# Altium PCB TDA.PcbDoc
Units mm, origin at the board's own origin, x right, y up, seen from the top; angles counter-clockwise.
Board outline 70 x 30 mm, 2 copper layers (Top Layer, Bottom Layer); 24 components, 16 nets, 55 pads, 0 vias.
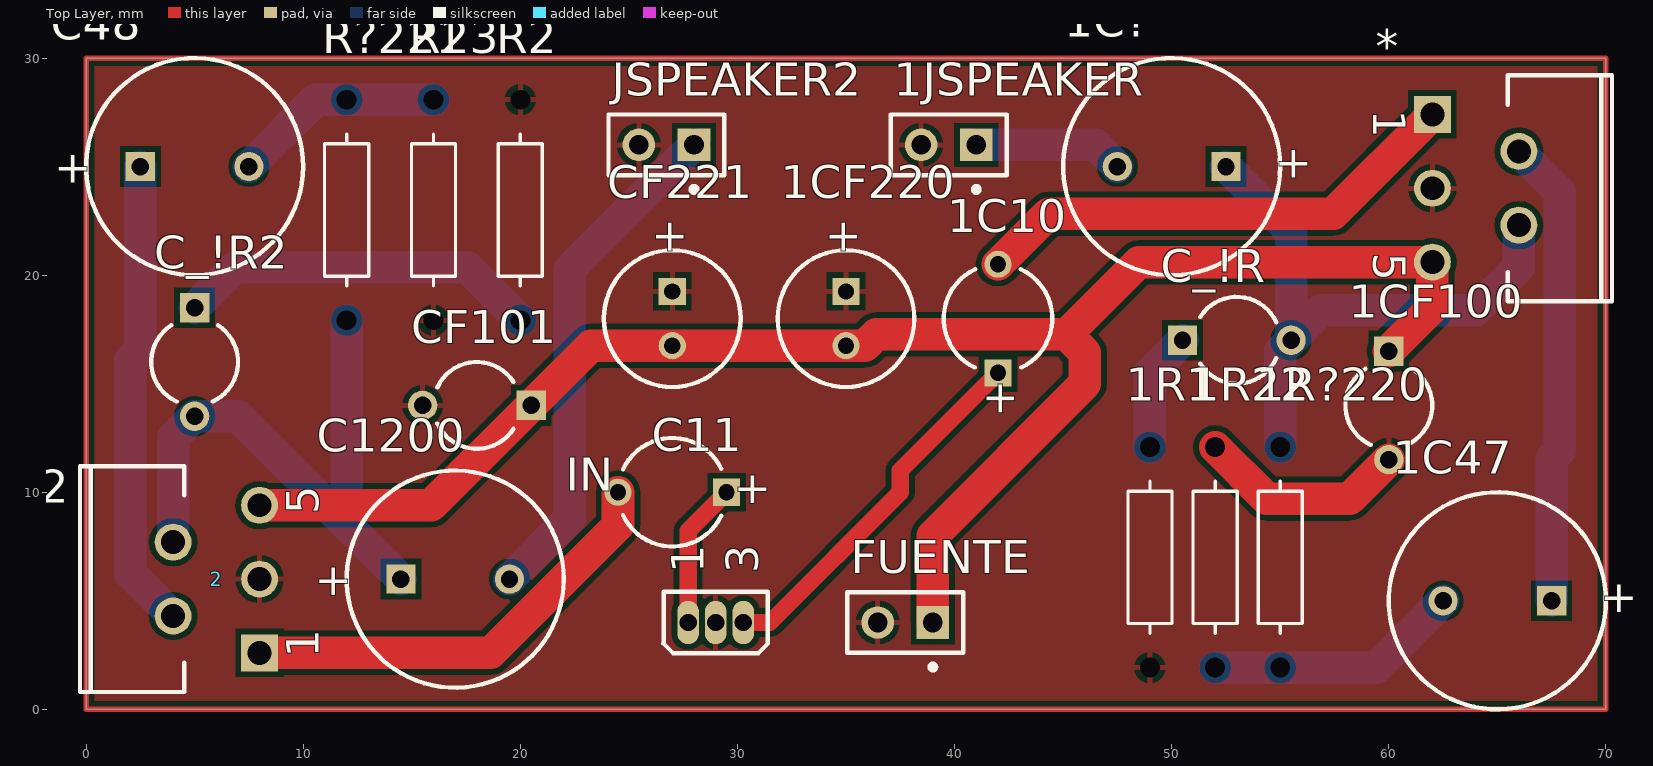
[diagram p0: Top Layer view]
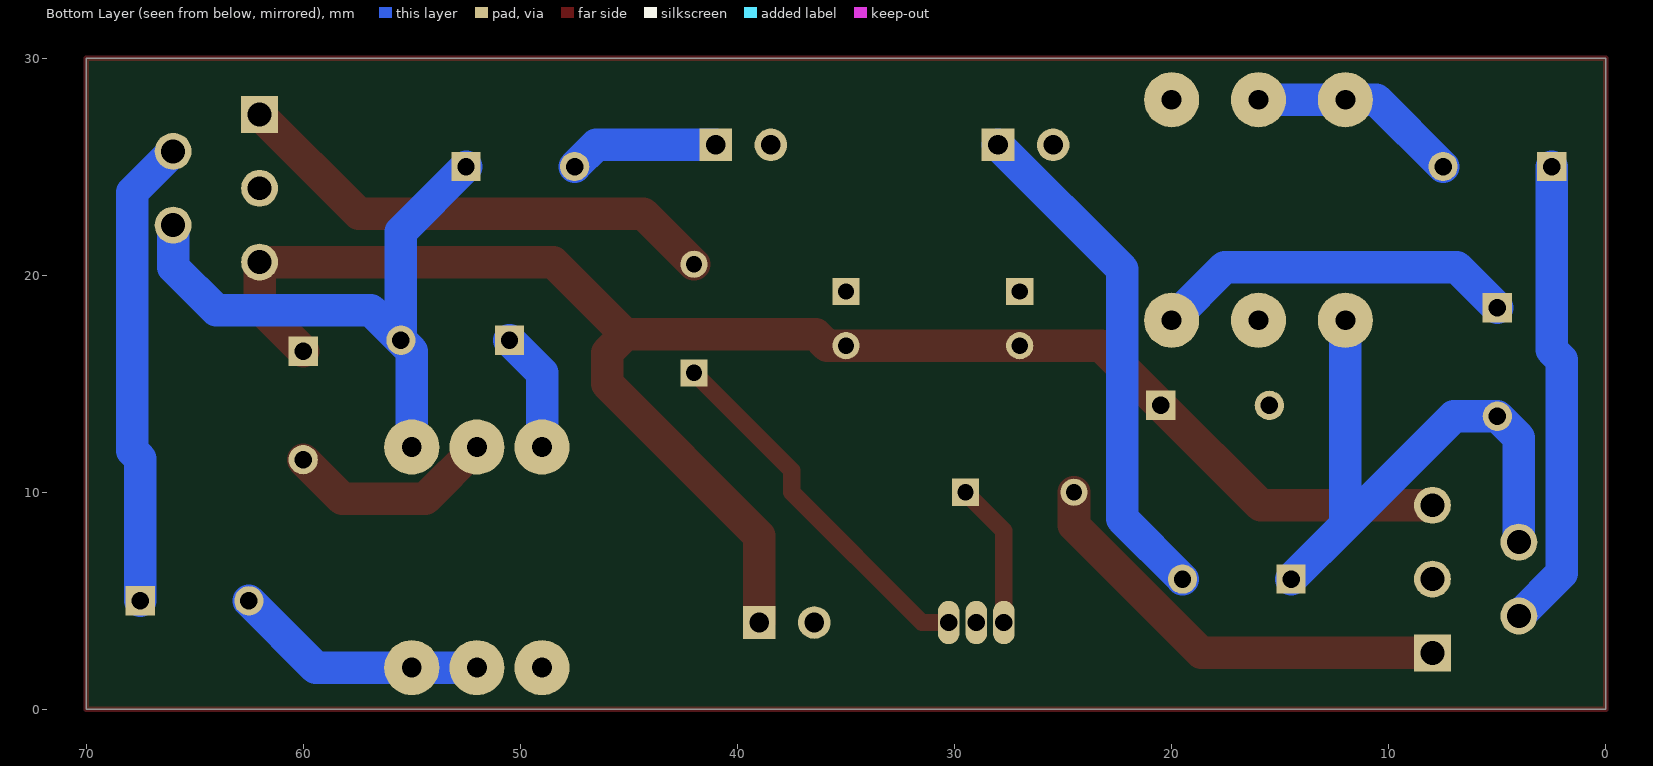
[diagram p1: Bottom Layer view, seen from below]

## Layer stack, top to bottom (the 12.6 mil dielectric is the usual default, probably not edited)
Top Solder: solder mask 0.0102, Solder Resist, Dk 3.5
Top Layer: signal copper 0.0356
Dielectric 1: dielectric 0.32, FR-4, Dk 4.8
Bottom Layer: signal copper 0.0356
Bottom Solder: solder mask 0.0102, Solder Resist, Dk 3.5

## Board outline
0,0 70,0 70,30 0,30

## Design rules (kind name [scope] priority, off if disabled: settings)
Clearance [All] p1: gap=0.254
PolygonConnect [All] p1: connectstyle=Relief reliefconductorwidth=0.254 reliefentries=4 polygonreliefangle="90 Angle" airgapwidth=0.254
RoomDefinition Tda2002 [InComponentClass('Tda2002')] p1: confinementstyle=ConfineIn formatcopy=TRUE lockcomponents=FALSE outline -25.4,-25.4 25.4,-25.4 25.4,0 -25.4,0
RoutingLayers RoutingLayers_arriba [InNetClass('arriba')] p1: top layer_v5=TRUE bottom layer_v5=FALSE
RoutingLayers [All] p2: top layer_v5=FALSE bottom layer_v5=TRUE
RoutingVias [All] p1: holewidth=0.711 width=1.27 viastyle="Through Hole" minholewidth=0.711 minwidth=1.27 maxholewidth=0.711 maxwidth=1.27
SolderMaskExpansion [All] p1: expansion=0.102
Width [All] p1: maxlimit=1.825 minlimit=0.254 preferedwidth=1.5
29 further rules are at their usual default settings.

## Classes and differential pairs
net class arriba: GND IN1 IN1FIL IN2 IN2FIL VCC

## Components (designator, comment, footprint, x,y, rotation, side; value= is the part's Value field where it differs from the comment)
1C10 "Cap 10" CAPPR5-5X7 42,18 r90 top
1C47 "Cap P470" cappr5-10x5 65,5 r180 top
1C? "Cap 1000" cappr5-10x5 50,25 r180 top
1CF100 "Cap Pol1" CAPR5-4X5 60,14 r270 top
1CF220 "Cap" cappr2.5-6.3x7 35,18 r270 top
1JSPEAKER "2P_TERM_BLOCK_HEADER" PIN2 41,26 r180 top
1R1 "Res2" RESTH_AXIAL-0.4 49,7 r270 top
1R22 "Res2" RESTH_AXIAL-0.4 52,7 r270 top
1R?220 "Res2" RESTH_AXIAL-0.4 55,7 r90 top
2 "TDA2002" PentawattV 6,6 r90 top
* "TDA2002" PentawattV 64,24 r270 top
C11 "Cap 10" CAPPR5-5X7 27,10 r180 top
C48 "Cap P470" cappr5-10x5 5,25 r0 top
C1200 "Cap 1000" cappr5-10x5 17,6 r0 top
C_!R "Cap" CAPR5-4X5 53,17 r0 top
C_!R2 "Cap" CAPR5-4X5 5,16 r270 top
CF101 "Cap Pol1" CAPR5-4X5 18,14 r180 top
CF221 "Cap" cappr2.5-6.3x7 27,18 r270 top
FUENTE "2P_TERM_BLOCK_HEADER" pin2 39,4 r180 top
IN "3P_TERM BLOCK HEADER" E3 29,4 r90 top
JSPEAKER2 "2P_TERM_BLOCK_HEADER" pin2 28,26 r180 top
R2 "Res2" RESTH_AXIAL-0.4 20,23 r90 top
R23 "Res2" RESTH_AXIAL-0.4 16,23 r90 top
R?221 "Res2w" RESTH_AXIAL-0.4 12,23 r270 top

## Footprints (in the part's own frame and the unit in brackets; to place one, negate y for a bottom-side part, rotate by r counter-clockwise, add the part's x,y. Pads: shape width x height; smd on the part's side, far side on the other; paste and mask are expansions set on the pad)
cappr2.5-6.3x7 [mm] "Capacitor, Electrolytic, Radial; Body 6.3 x 7 mm (Dia.xH typ); Pin Spacing 2.5 mm (typ)"
  rect 1.25x1.25 hole 0.75: 1(-1.25,0)
  round 1.25 hole 0.75: 2(1.25,0)
  silkscreen extent -3.15,-3.15 3.15,3.15
CAPPR5-5X7 [mm] "Capacitor, Electrolytic, Radial; Body 5 x 7 mm (Dia.xH typ); Pin Spacing 5 mm (typ)"
  rect 1.25x1.25 hole 0.75: 1(-2.5,0)
  round 1.25 hole 0.75: 2(2.5,0)
  silkscreen extent -2.26,-2.5 2.27,2.5
cappr5-10x5 [mm] "Capacitor, Electrolytic, Radial; Body 10 x 5 mm (Dia.xH typ); Pin Spacing 5 mm (typ)"
  rect 1.35x1.35 hole 0.8: 1(-2.5,0)
  round 1.35 hole 0.8: 2(2.5,0)
  silkscreen extent -5,-5 5,5
CAPR5-4X5 [mm] "Capacitor; 2 Leads"
  rect 1.35x1.35 hole 0.8: 1(-2.5,0)
  round 1.35 hole 0.8: 2(2.5,0)
  silkscreen extent -1.69,-2 1.82,2
E3 [mm] "TO, Flat Index; 3 In-Line, Axial Leads; Body Dia. 4.6mm; Lead Dia. 0.5 mm (max)"
  oval 2x1 hole 0.8: 1(0,1.27) 2(0,0) 3(0,-1.27)
  silkscreen extent -1.41,-2.41 1.41,2.41
PentawattV [mm] "TO, Thru-Hole, Vertical, Heatsink Mounted; 5 Bent Staggered Leads; Pitch 1.7 mm"
  rect 1.7x1.7 hole 1.1: 1(-3.4,-1.99)
  round 1.7 hole 1.1: 2(-1.7,1.99) 3(0,-1.99) 4(1.7,1.99) 5(3.4,-1.99)
  silkscreen extent -5.2,1.48 5.2,6.28
PIN2 [mm] "Photosensitive Diode; 2 Leads"
  rect 1.5x1.5 hole 0.9: 1(0,0)
  round 1.5 hole 0.9: 2(2.54,0)
  silkscreen extent -1.4,-1.4 3.94,2.17
pin2 [mm] "Photosensitive Diode; 2 Leads"
  rect 1.5x1.5 hole 0.9: 1(0,0)
  round 1.5 hole 0.9: 2(2.54,0)
  silkscreen extent -1.4,-1.4 3.94,2.17
RESTH_AXIAL-0.4 [mil]
  round 0 / inner round 0 / far side round 100 hole 36 unplated: 1(-200,0) 2(200,0)
  silkscreen extent -138,-40 138,40, body extent -212,-50 212,50, height 102

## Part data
1C10 1C47 1C? C11 C48 C1200: library part "Cap Pol1", "Polarized Capacitor (Radial)"
1CF100 CF101: "Polarized Capacitor (Radial)"
1CF220 C_!R C_!R2 CF221: "Capacitor"
1JSPEAKER FUENTE JSPEAKER2: "Terminal Block THT 2-position header 3.81mm pitch"
1R1 1R22 1R?220 R2 R23: "Resistor"
IN: "Terminal Block THT 3-Position header 3.81mm pitch"
R?221: library part Res2, "Resistor"

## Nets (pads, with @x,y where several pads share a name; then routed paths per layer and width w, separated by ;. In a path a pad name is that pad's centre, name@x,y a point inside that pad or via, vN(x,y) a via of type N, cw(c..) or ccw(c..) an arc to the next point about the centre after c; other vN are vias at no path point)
GND: 1CF100.2 1CF220.1 1JSPEAKER.2 1R1.2 1R22.1 2.3 *.3 CF101.2 CF221.1 FUENTE.2 IN.2 JSPEAKER2.2 R2.2 R23.1 | length 9.7
  Top Layer w1.5: 1R22.1 54.377,9.703 58.203,9.703 1CF100.2
IN1: 1C10.1 IN.3 | length 17.1
  Top Layer w0.8: IN.3 31.5,4 37.5,10 37.5,11 1C10.1
IN1FIL: 1C10.2 *.1 | length 22.9
  Top Layer w1.5: 1C10.2 44.335,22.835 57.445,22.835 *.1
IN2: C11.1 IN.1 | length 6.7
  Top Layer w0.8: IN.1 27.73,8.23 C11.1
IN2FIL: 2.1 C11.2 | length 20.5
  Top Layer w1.5: 2.1 18.627,2.6 24.5,8.473 C11.2
Net1C47_2: 1C47.2 1R22.2 1R?220.1 | length 11.8
  Bottom Layer w1.5: 1R22.2 1R?220.1 59.42,1.92 1C47.2
Net1C?_2: 1C?.2 1JSPEAKER.1 | length 6.9
  Bottom Layer w1.5: 1JSPEAKER.1 46.5,26 1C?.2
Net1R1_1: 1R1.1 C_!R.1 | length 5.5
  Bottom Layer w1.5: 1R1.1 49,15.5 C_!R.1
Net2_2: 2.2 C48.1 | length 21.7
  Bottom Layer w1.5: C48.1 2.5,16.561 2.032,16.093 2.032,6.278 2.2
Net2_4: 2.4 C1200.1 C_!R2.2 R?221.2 | length 28.2
  Bottom Layer w1.5: 2.4 4.01,12.51 C_!R2.2 7,13.5 12,8.5 ; R?221.2 12,8.5 ; C1200.1 12,8.5
Net*_2: 1C47.1 *.2 | length 21.6
  Bottom Layer w1.5: *.2 67.869,23.821 67.869,11.913 67.5,11.544 1C47.1
Net*_4: 1C?.1 1R?220.2 *.4 C_!R.2 | length 28.2
  Bottom Layer w1.5: 1C?.1 55.5,22 C_!R.2 ; 1R?220.2 55,16.5 C_!R.2 ; *.4 65.99,20.372 64.008,18.39 56.89,18.39 C_!R.2
NetC48_2: C48.2 R23.2 R?221.1 | length 9.8
  Bottom Layer w1.5: C48.2 10.58,28.08 R?221.1 R23.2
NetC1200_2: C1200.2 JSPEAKER2.1 | length 23.5
  Bottom Layer w1.5: C1200.2 22.276,8.776 22.276,20.276 JSPEAKER2.1
NetC_!R2_1: C_!R2.1 R2.1 | length 16.8
  Bottom Layer w1.5: C_!R2.1 6.867,20.367 17.553,20.367 R2.1
VCC: 1CF100.1 1CF220.2 2.5 *.5 CF101.1 CF221.2 FUENTE.1 | length 80.1
  Top Layer w1.5: 2.5 15.9,9.4 CF101.1 23.25,16.75 CF221.2 1CF220.2 35.865,16.75 36.387,17.272 45.161,17.272 ; FUENTE.1 39,8 46,15 46,16.433 45.161,17.272 ; 1CF100.1 62.01,18.51 *.5 48.489,20.6 45.161,17.272
copper on no net: | length 200
  Top Layer w0.254: 0,0 70,0 70,30 0,30 0,0

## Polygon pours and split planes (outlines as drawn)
GND on Top Layer "GND" (solid, pour order 2): 0,30 70,30 70,0 0,0 0,30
